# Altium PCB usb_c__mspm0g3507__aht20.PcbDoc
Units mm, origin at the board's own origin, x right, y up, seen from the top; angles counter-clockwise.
Board outline 68 x 40 mm, 2 copper layers (Top, Bottom), stack 0 mm thick; 38 components, 33 nets, 190 pads, 51 vias.
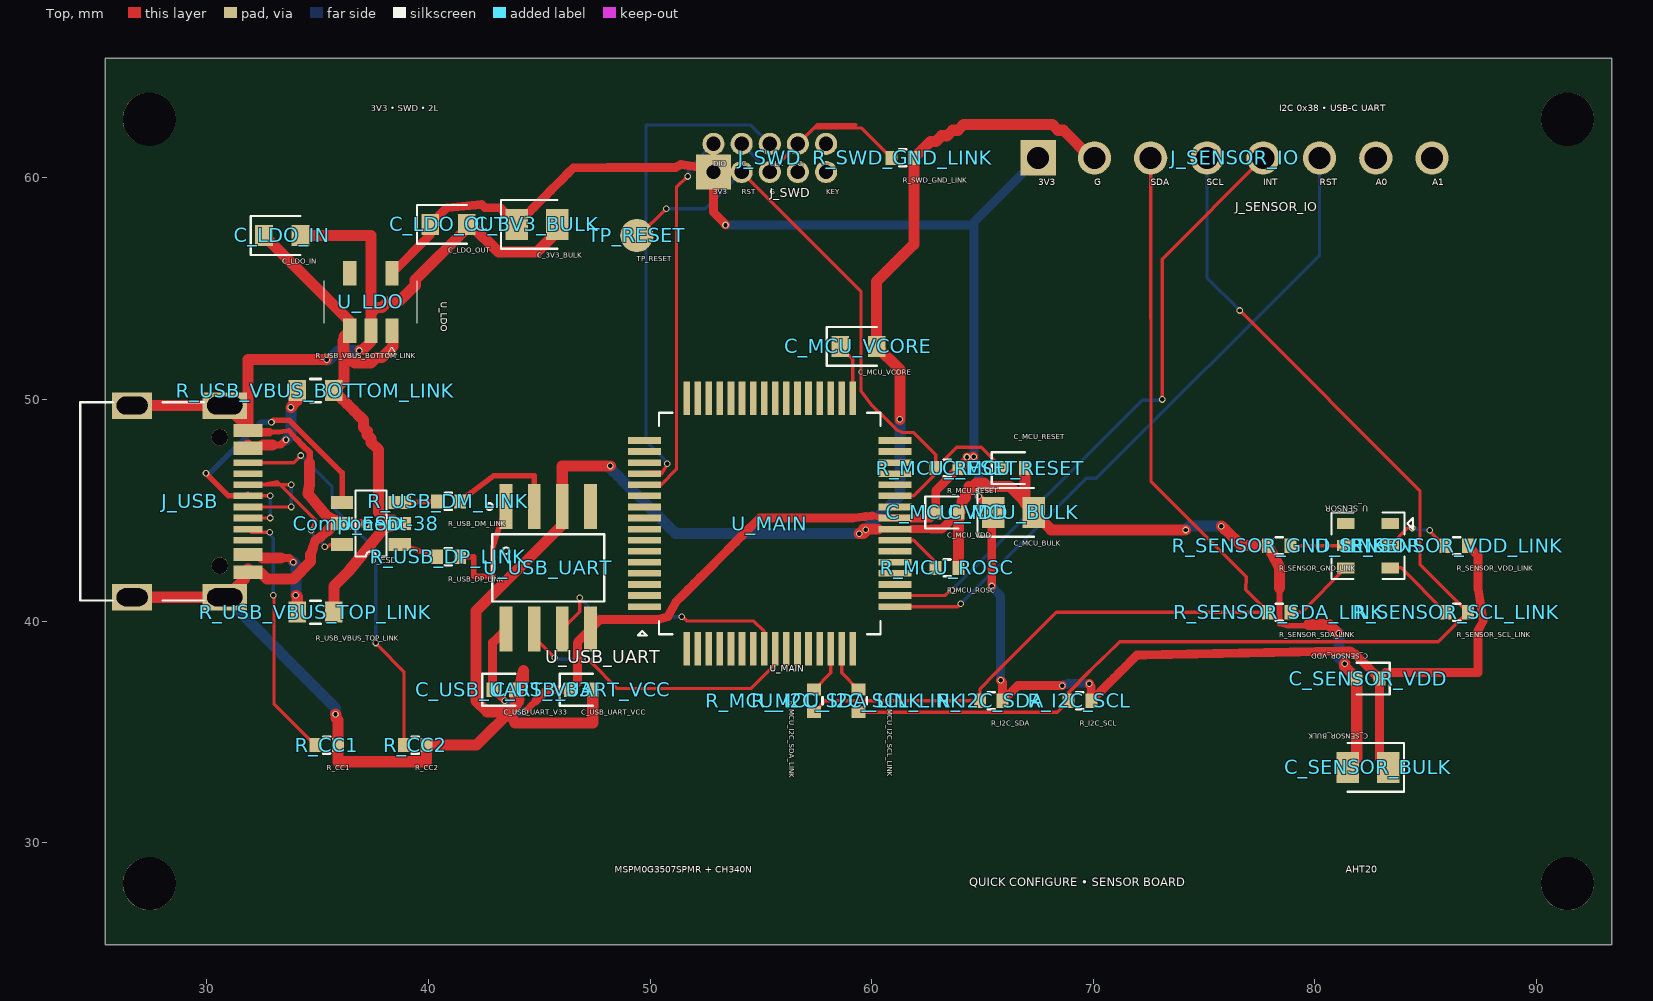
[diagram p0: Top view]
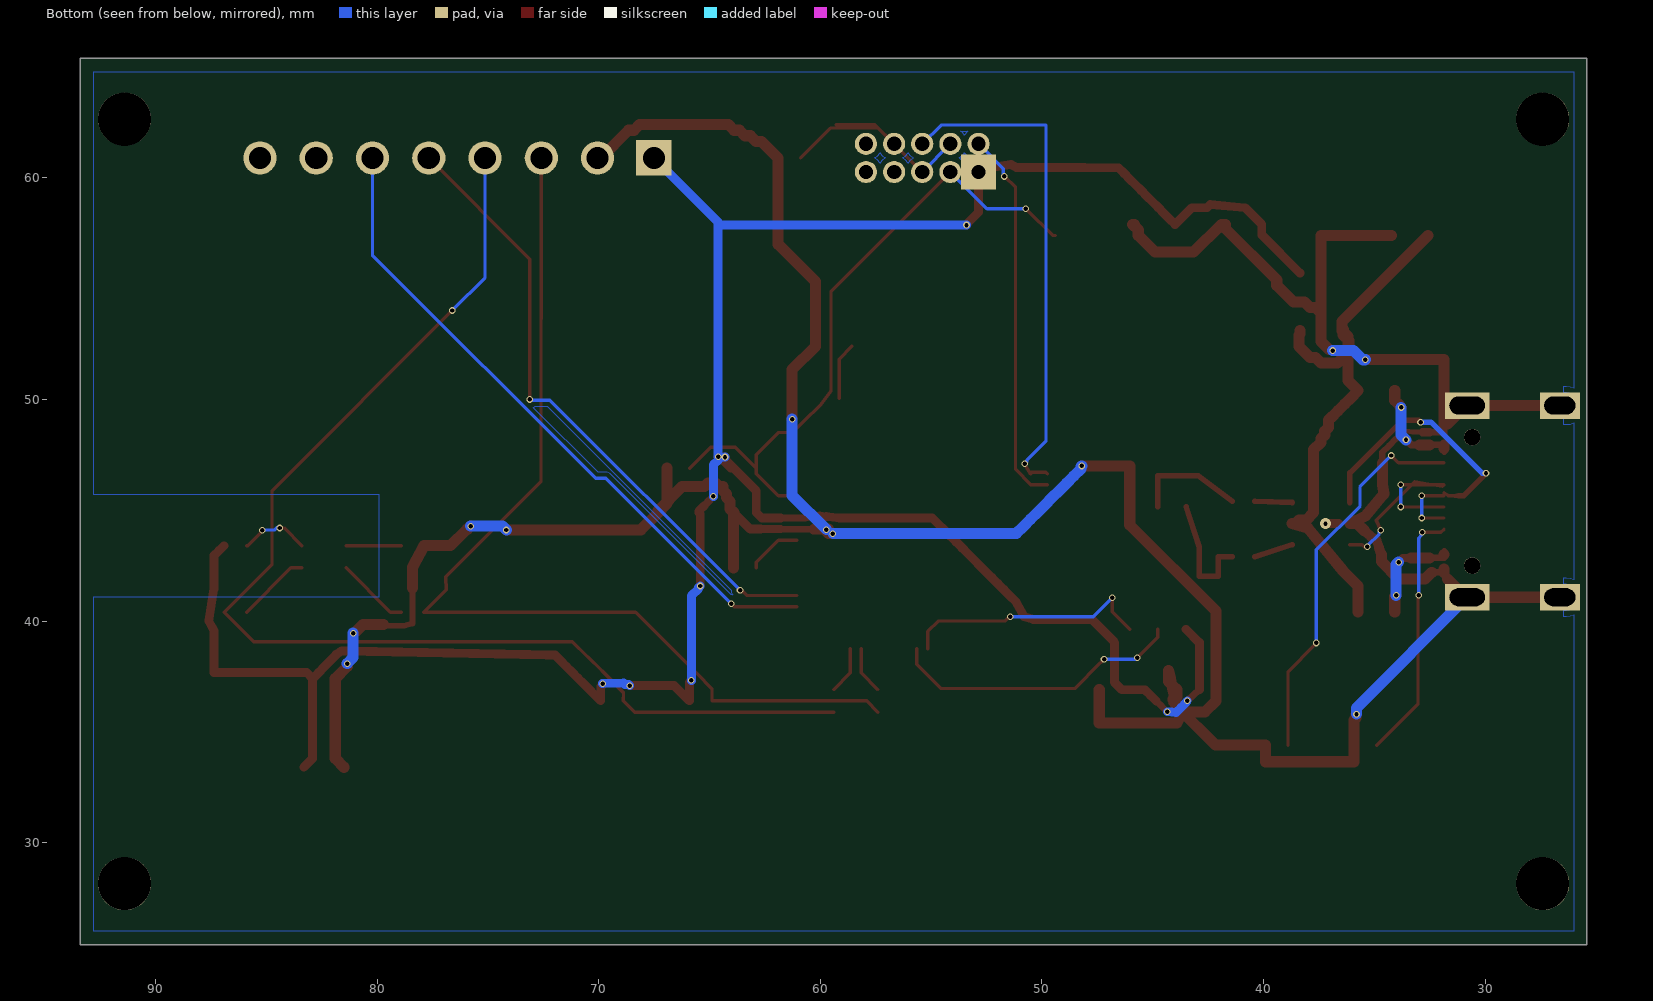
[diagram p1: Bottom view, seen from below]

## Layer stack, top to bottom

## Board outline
25.4,65.4 93.4,65.4 93.4,25.4 25.4,25.4

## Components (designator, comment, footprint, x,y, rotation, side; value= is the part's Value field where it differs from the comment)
C_3V3_BULK "" TSCIRCUIT-2.8500x1.4000mm 44.9,57.9 r0 top
C_LDO_IN "" TSCIRCUIT-2.4500x0.9500mm 33.4,57.4 r0 top
C_LDO_OUT "" TSCIRCUIT-2.4500x0.9500mm 40.9,57.9 r0 top
C_MCU_BULK "" TSCIRCUIT-2.8500x1.4000mm 66.4,44.9 r0 top
C_MCU_RESET "" TSCIRCUIT-1.5600x0.6400mm 66.4,46.9 r0 top
C_MCU_VCORE "" TSCIRCUIT-2.4500x0.9500mm 59.4,52.4 r0 top
C_MCU_VDD "" TSCIRCUIT-1.5600x0.6400mm 63.4,44.9 r0 top
C_SENSOR_BULK "" TSCIRCUIT-2.8500x1.4000mm 82.4,33.4 r180 top
C_SENSOR_VDD "" TSCIRCUIT-1.5600x0.6400mm 82.4,37.4 r180 top
C_USB_UART_V33 "" TSCIRCUIT-1.5600x0.6400mm 43.4,36.9 r0 top
C_USB_UART_VCC "" TSCIRCUIT-1.5600x0.6400mm 46.9,36.9 r0 top
Component-38 "" TSCIRCUIT-0.5000x0.5000mm 37.2,44.4 r0 top
J_SENSOR_IO "" TSCIRCUIT-19.2800x1.5000mm 76.4,60.9 r0 top
J_SWD "" TSCIRCUIT-6.0800x2.2700mm 55.4,60.9 r0 top
J_USB "" TSCIRCUIT-6.7732x9.8502mm 29.112,45.4 r90 top
R_CC1 "" TSCIRCUIT-1.5600x0.6400mm 35.4,34.4 r0 top
R_CC2 "" TSCIRCUIT-1.5600x0.6400mm 39.4,34.4 r0 top
R_I2C_SCL "" TSCIRCUIT-1.5600x0.6400mm 69.4,36.4 r0 top
R_I2C_SDA "" TSCIRCUIT-1.5600x0.6400mm 65.4,36.4 r0 top
R_MCU_I2C_SCL_LINK "" TSCIRCUIT-0.6400x1.5600mm 59.4,36.4 r270 top
R_MCU_I2C_SDA_LINK "" TSCIRCUIT-0.6400x1.5600mm 57.4,36.4 r270 top
R_MCU_RESET "" TSCIRCUIT-1.5600x0.6400mm 63.4,46.9 r0 top
R_MCU_ROSC "" TSCIRCUIT-1.5600x0.6400mm 63.4,42.4 r0 top
R_SENSOR_GND_LINK "" TSCIRCUIT-1.5600x0.6400mm 78.4,43.4 r0 top
R_SENSOR_SCL_LINK "" TSCIRCUIT-1.5600x0.6400mm 86.4,40.4 r0 top
R_SENSOR_SDA_LINK "" TSCIRCUIT-1.5600x0.6400mm 78.4,40.4 r0 top
R_SENSOR_VDD_LINK "" TSCIRCUIT-1.5600x0.6400mm 86.4,43.4 r0 top
R_SWD_GND_LINK "" TSCIRCUIT-1.5600x0.6400mm 61.4,60.9 r0 top
R_USB_DM_LINK "" TSCIRCUIT-1.5600x0.6400mm 40.9,45.4 r0 top
R_USB_DP_LINK "" TSCIRCUIT-1.5600x0.6400mm 40.9,42.9 r0 top
R_USB_VBUS_BOTTOM_LINK "" TSCIRCUIT-2.4500x0.9500mm 34.9,50.4 r0 top
R_USB_VBUS_TOP_LINK "" TSCIRCUIT-2.4500x0.9500mm 34.9,40.4 r0 top
TP_RESET "" TSCIRCUIT-1.5000x1.5000mm 49.4,57.4 r0 top
U_ESD "" TSCIRCUIT-3.6000x2.5000mm 37.4,44.4 r0 top
U_LDO "" TSCIRCUIT-2.5000x3.7000mm 37.4,54.4 r270 top
U_MAIN "" TSCIRCUIT-12.8000x12.8000mm 55.4,44.4 r0 top
U_SENSOR "" TSCIRCUIT-2.8000x2.5000mm 82.4,43.4 r0 top
U_USB_UART "" TSCIRCUIT-4.3840x7.5712mm 45.4,42.4 r0 top

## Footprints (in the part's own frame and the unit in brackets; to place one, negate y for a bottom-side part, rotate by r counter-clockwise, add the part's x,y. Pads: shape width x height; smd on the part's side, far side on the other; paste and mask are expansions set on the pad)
TSCIRCUIT-0.5000x0.5000mm [mm]
TSCIRCUIT-0.6400x1.5600mm [mm]
  rect 0.54x0.64 smd: 1(-0.51,0) 2(0.51,0)
  silkscreen extent -0.15,-0.38 0.15,0.38
TSCIRCUIT-1.5000x1.5000mm [mm]
  round 1.5 smd: 1(0,0)
TSCIRCUIT-1.5600x0.6400mm [mm]
  rect 0.54x0.64 smd: 1(-0.51,0) 2(0.51,0)
  silkscreen extent -0.98,-0.72 0.51,0.72
TSCIRCUIT-2.4500x0.9500mm [mm]
  rect 0.8x0.95 smd: 1(-0.825,0) 2(0.825,0)
  silkscreen extent -1.42,-0.87 0.82,0.87
TSCIRCUIT-2.5000x3.7000mm [mm]
  rect 1.1x0.6 smd: 1(1.3,0.95) 2(1.3,0) 3(1.3,-0.95) 4(-1.3,-0.95) 5(-1.3,0.95)
  silkscreen extent -0.95,-2.1 2.35,2.1
TSCIRCUIT-2.8000x2.5000mm [mm]
  rect 0.8x0.5 smd: 1(1,1) 2(1,0) 3(1,-1) 4(-1,-1) 5(-1,0) 6(-1,1)
  silkscreen extent -1.65,-1.5 2.02,1.5
TSCIRCUIT-2.8500x1.4000mm [mm]
  rect 1.025x1.4 smd: 1(-0.913,0) 2(0.913,0)
  silkscreen extent -1.62,-1.1 0.91,1.1
TSCIRCUIT-3.6000x2.5000mm [mm]
  rect 1x0.6 smd: 1(-1.3,-0.95) 2(-1.3,0) 3(-1.3,0.95) 4(1.3,0.95) 5(1.3,0) 6(1.3,-0.95)
  silkscreen extent -0.7,-1.49 0.7,1.49
TSCIRCUIT-4.3840x7.5712mm [mm]
  rect 0.574x2.036 smd: 1(-1.905,2.768) 2(-0.635,2.768) 3(0.635,2.768) 4(1.905,2.768) 5(1.905,-2.768) 6(0.635,-2.768) 7(-0.635,-2.768) 8(-1.905,-2.768)
  silkscreen extent -2.79,-1.52 2.53,2.92
TSCIRCUIT-6.0800x2.2700mm [mm]
  rect 1.6x1.6 hole 0.65: 1(-2.54,-0.635)
  round 1 hole 0.65: 2(-2.54,0.635) 3(-1.27,0.635) 4(0,0.635) 5(1.27,0.635) 6(2.54,0.635) 7(2.54,-0.635) 8(1.27,-0.635) 9(0,-0.635) 10(-1.27,-0.635)
TSCIRCUIT-6.7732x9.8502mm [mm]
  rect 0.3x1.3 smd: 1(-3.35,-2.737) 2(-3.05,-2.737) 3(-2.55,-2.737) 4(-2.25,-2.737) 5(-1.75,-2.737) 6(-1.25,-2.737) 7(-0.75,-2.737) 8(-0.25,-2.737) 9(0.25,-2.737) 10(0.75,-2.737) 11(1.25,-2.737) 12(1.75,-2.737) 13(2.55,-2.737) 14(2.25,-2.737) 15(3.35,-2.737) 16(3.05,-2.737)
  rect 1.2x2 hole 0.8 slot 1.6 at 90 deg: 17(-4.325,-1.693) 18(4.325,-1.693)
  rect 1.2x1.8 hole 0.8 slot 1.4 at 90 deg: 19(4.325,2.487) 20(-4.325,2.487)
  round 0.75 hole 0.75 unplated: NPTH-1(-2.9,-1.468) NPTH-2(2.9,-1.468)
  silkscreen extent -4.47,-0.75 4.47,4.83
TSCIRCUIT-12.8000x12.8000mm [mm]
  rect 1.5x0.3 smd: 1(-5.65,-3.75) 2(-5.65,-3.25) 3(-5.65,-2.75) 4(-5.65,-2.25) 5(-5.65,-1.75) 6(-5.65,-1.25) 7(-5.65,-0.75) 8(-5.65,-0.25) 9(-5.65,0.25) 10(-5.65,0.75) 11(-5.65,1.25) 12(-5.65,1.75) 13(-5.65,2.25) 14(-5.65,2.75) 15(-5.65,3.25) 16(-5.65,3.75) 33(5.65,3.75) 34(5.65,3.25) 35(5.65,2.75) 36(5.65,2.25) 37(5.65,1.75) 38(5.65,1.25) 39(5.65,0.75) 40(5.65,0.25) 41(5.65,-0.25) 42(5.65,-0.75) 43(5.65,-1.25) 44(5.65,-1.75) 45(5.65,-2.25) 46(5.65,-2.75) 47(5.65,-3.25) 48(5.65,-3.75)
  rect 0.3x1.5 smd: 17(-3.75,5.65) 18(-3.25,5.65) 19(-2.75,5.65) 20(-2.25,5.65) 21(-1.75,5.65) 22(-1.25,5.65) 23(-0.75,5.65) 24(-0.25,5.65) 25(0.25,5.65) 26(0.75,5.65) 27(1.25,5.65) 28(1.75,5.65) 29(2.25,5.65) 30(2.75,5.65) 31(3.25,5.65) 32(3.75,5.65) 49(3.75,-5.65) 50(3.25,-5.65) 51(2.75,-5.65) 52(2.25,-5.65) 53(1.75,-5.65) 54(1.25,-5.65) 55(0.75,-5.65) 56(0.25,-5.65) 57(-0.25,-5.65) 58(-0.75,-5.65) 59(-1.25,-5.65) 60(-1.75,-5.65) 61(-2.25,-5.65) 62(-2.75,-5.65) 63(-3.25,-5.65) 64(-3.75,-5.65)
  silkscreen extent -5.95,-5.05 5,5
TSCIRCUIT-19.2800x1.5000mm [mm]
  rect 1.6x1.6 hole 1: 1(-8.89,0)
  round 1.5 hole 1: 2(-6.35,0) 3(-3.81,0) 4(-1.27,0) 5(1.27,0) 6(3.81,0) 7(6.35,0) 8(8.89,0)

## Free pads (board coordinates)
  round 2.4 hole 2.4 unplated: NPTH-3(27.4,28.15) NPTH-4(91.4,28.15) NPTH-5(27.4,62.65) NPTH-6(91.4,62.65)

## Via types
v1: diameter 0.3, hole 0.2, Top to Bottom, 50 vias
v2: diameter 0.5, hole 0.2, Top to Bottom, 1 vias

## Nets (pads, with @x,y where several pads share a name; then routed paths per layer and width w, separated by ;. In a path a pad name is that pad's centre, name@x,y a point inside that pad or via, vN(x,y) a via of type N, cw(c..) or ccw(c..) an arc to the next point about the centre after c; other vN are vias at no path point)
".J_SWD > .pin2 to .U_MAIN > .pin12": J_SWD.2 U_MAIN.12 | length 17.1
  Top w0.15: U_MAIN.12 50.496,46.15 51.188,46.842 51.188,59.575 v1(51.697,60.066)
  Bottom w0.15: v1(51.697,60.066) 51.741,60.128 51.741,60.248 51.741,60.416 J_SWD.2
".J_SWD > .pin4 to .U_MAIN > .pin13": J_SWD.4 U_MAIN.13 | length 23
  Top w0.15: U_MAIN.13 49.817,46.717 50.519,46.717 50.509,46.646 50.708,46.977 v1(50.775,47.104)
  Bottom w0.15: v1(50.775,47.104) 50.687,47.192 50.687,47.246 49.816,48.117 49.816,62.384 54.551,62.384 J_SWD.4
".U_MAIN > .pin42 to .R_MCU_ROSC > .pin1": R_MCU_ROSC.1 U_MAIN.42 | length 2.5
  Top w0.15: U_MAIN.42 61.889,43.65 62.89,42.649 R_MCU_ROSC.1
AHT_GND_LOCAL: R_SENSOR_GND_LINK.2 U_SENSOR.5 | length 2.5
  Top w0.15: R_SENSOR_GND_LINK.2 U_SENSOR.5
AHT_SCL_LOCAL: R_SENSOR_SCL_LINK.1 U_SENSOR.3 | length 3.3
  Top w0.15: U_SENSOR.3 83.89,42.4 R_SENSOR_SCL_LINK.1
AHT_SDA_LOCAL: R_SENSOR_SDA_LINK.2 U_SENSOR.4 | length 3.3
  Top w0.15: R_SENSOR_SDA_LINK.2 79.4,40.4 U_SENSOR.4
AHT_VDD_LOCAL: R_SENSOR_VDD_LINK.1 U_SENSOR.2 | length 3.2
  Top w0.15: U_SENSOR.2 84.2,44.2 v1(84.4,44.2) ; v1(85.189,44.105) 85.193,44.101 85.193,44.051 85.844,43.4 R_SENSOR_VDD_LINK.1
  Bottom w0.15: v1(84.4,44.2) 84.443,44.243 84.498,44.243 84.635,44.105 v1(85.189,44.105)
GND: C_3V3_BULK.2 C_LDO_IN.2 C_LDO_OUT.2 C_MCU_BULK.2 C_MCU_RESET.2 C_MCU_VCORE.2 C_MCU_VDD.2 C_SENSOR_BULK.2 C_SENSOR_VDD.2 C_USB_UART_V33.2 C_USB_UART_VCC.2 J_SENSOR_IO.2 J_USB.1 J_USB.2 J_USB.15 J_USB.16 J_USB.17 J_USB.18 J_USB.19 J_USB.20 R_CC1.2 R_CC2.2 R_MCU_ROSC.2 R_SENSOR_GND_LINK.1 R_SWD_GND_LINK.2 U_ESD.2 U_LDO.2 U_MAIN.41 U_USB_UART.3 | length 181.6
  Top w0.225: 32.823,48.524 33.276,48.526 33.7,48.6 33.865,48.412 34.03,48.224
  Top w0.25: 78.4,39.9 78.765,39.792 79.658,39.792
  Top w0.275: J_USB.16 J_USB.16@31.918,48.52 ; 34.03,48.224 34.331,47.92 34.632,47.616 ; 78.4,39.9 78.4,40.237 78.4,40.575 78.4,41.038 78.4,41.501 ; 79.658,39.792 79.712,39.846
  Top w0.3: J_USB.1@31.699,41.9 J_USB.1 J_USB.1@31.849,42.2 ; J_USB.15@31.699,48.9 J_USB.15 ; J_USB.16@31.849,48.6 J_USB.15 ; J_USB.15@31.849,48.9 J_USB.15 ; J_USB.2@31.995,42.204 32.001,42.198 J_USB.1@32.406,42.198 ; 34.632,47.133 34.632,47.616 ; 60.238,44.15 60.644,44.15 U_MAIN.41 ; U_MAIN.41@60.3,44.15 60.58,44.15 U_MAIN.41 ; 61.8,44.15 61.706,44.15 61.613,44.15 61.519,44.15 61.425,44.15 61.331,44.15 61.238,44.15 61.144,44.15 U_MAIN.41
  Top w0.306: J_USB.16@31.918,48.52 32.371,48.522 J_USB.16@32.499,48.522
  Top w0.325: J_USB.2 J_USB.2@31.995,42.204 ; J_USB.16 J_USB.16@31.849,48.6
  Top w0.375: 32.499,48.522 32.823,48.524 ; 61.8,44.15 62.253,44.15 62.707,44.15
  Top w0.4: 36.6,44.4 37.2,44.4 ; v1(36.878,52.207) v1@36.879,52.252 ; 62.707,44.15 63.16,44.15 63.41,44.4 63.66,44.65 C_MCU_VDD.2
  Top w0.425: v1@36.879,52.252 37.034,52.252 ; 80.949,39.534 80.999,39.534 v1(81.082,39.451)
  Top w0.437: 34.791,43.322 34.9,43.65 35.138,43.799
  Top w0.45: 34.681,42.994 34.791,43.322 ; 35.138,43.799 35.439,44.073
  Top w0.475: v1@59.831,44.15 60.238,44.15 ; 60.109,44.15 60.3,44.15
  Top w0.5: J_USB.20 J_USB.17 ; J_USB.19 J_USB.18 ; J_USB.17 30.874,41.075 31.474,41.675 31.699,41.9 ; J_USB.18 30.874,49.725 31.474,49.125 31.699,48.9 ; J_USB.1@31.849,42.2 J_USB.2 ; 31.849,48.9 31.849,51.8 v1(35.4,51.8) ; J_USB.1@32.406,42.198 32.703,41.9 33.9,41.9 34.681,42.681 34.681,42.994 ; C_LDO_IN.2 37.4,57.4 U_LDO.2 ; 34.632,47.133 34.632,46.649 34.632,46.166 34.567,45.733 35.4,44.733 U_ESD.2 35.78,44.406 35.439,44.073 ; v1(35.8,35.8) 35.83,35.77 35.83,35.617 35.91,35.537 R_CC1.2 35.91,33.65 39.91,33.65 R_CC2.2 42.166,34.4 43.869,36.103 44.087,36.431 ; 37.034,52.252 37.217,52.435 37.4,52.618 U_LDO.2 ; C_3V3_BULK.2 45.9,57.9 45.65,57.65 45.65,57.4 44.9,56.65 43.15,56.65 41.9,57.9 C_LDO_OUT.2 41.725,57.725 39.4,55.4 39.4,55.15 38.65,54.4 38.15,54.4 37.9,54.15 37.65,54.15 37.4,53.9 U_LDO.2 ; C_USB_UART_VCC.2 47.41,35.4 43.9,35.4 43.65,35.9 ; v1(48.2,47) 46.035,47 U_USB_UART.3 46.035,44.749 46.035,44.33 42.15,40.445 42.15,36.4 42.65,35.9 43.65,35.9 ; v1(59.434,43.945) 59.44,43.951 59.633,43.951 v1@59.831,44.15 ; v1(59.725,44.125) 59.664,44.125 59.639,44.15 60.109,44.15 ; v1(61.271,49.107) 61.271,51.354 C_MCU_VCORE.2 60.225,52.887 60.225,53.374 60.225,53.86 60.225,54.347 60.225,54.834 60.225,55.321 61.91,57.006 R_SWD_GND_LINK.2 62.247,61.237 62.584,61.574 62.65,61.64 62.65,61.65 62.9,61.65 63.15,61.9 63.4,61.9 63.65,62.15 63.9,62.15 64.15,62.4 68.15,62.4 68.4,62.15 68.65,62.15 69.9,60.9 J_SENSOR_IO.2 ; R_MCU_ROSC.2 C_MCU_VDD.2 63.9,44.9 64.067,45.067 64.067,45.4 64.233,45.567 64.233,45.733 64.4,45.9 64.4,46.067 64.567,46.067 64.733,46.233 65.067,46.233 65.233,46.067 66.233,46.067 67.312,44.988 C_MCU_BULK.2 ; C_MCU_RESET.2 66.91,45.303 C_MCU_BULK.2 ; v1(74.169,44.108) 68.104,44.108 C_MCU_BULK.2 ; v1(75.778,44.285) 75.92,44.143 75.948,44.143 76.691,43.4 R_SENSOR_GND_LINK.1 78.4,42.427 78.4,41.964 78.4,41.501 ; 79.712,39.846 80.175,39.846 80.637,39.846 80.949,39.534 ; v1(81.349,38.079) 81.349,37.941 C_SENSOR_VDD.2 81.89,33.803 C_SENSOR_BULK.2 ; 43.65,35.9 43.9,36.15 44.087,36.431 ; 43.65,35.9 43.817,36.067 43.942,36.213 44.028,36.603 44.114,36.993 44.201,37.383 44.287,37.773 44.287,37.277 44.098,37.088 C_USB_UART_V33.2 ; C_USB_UART_V33.2 43.999,36.666 44.087,36.431 ; C_USB_UART_V33.2 43.912,36.582 44.087,36.431
  Bottom w0.5: J_USB.17 35.8,36.081 v1(35.8,35.8) ; v1(35.4,51.8) 35.423,51.777 35.505,51.777 35.72,51.992 35.935,52.207 36.406,52.207 v1(36.878,52.207) ; v1(48.2,47) 48.237,46.963 48.237,46.866 48.562,46.542 48.886,46.217 49.211,45.893 49.535,45.568 49.86,45.243 50.185,44.919 50.509,44.594 50.834,44.27 51.158,43.945 51.645,43.945 52.132,43.945 52.619,43.945 53.106,43.945 53.592,43.945 54.079,43.945 54.566,43.945 55.053,43.945 55.54,43.945 56.026,43.945 56.513,43.945 57,43.945 57.487,43.945 57.974,43.945 58.46,43.945 58.947,43.945 v1(59.434,43.945) ; v1(59.725,44.125) 61.271,45.671 v1(61.271,49.107) ; v1(74.169,44.108) 74.346,44.285 v1(75.778,44.285) ; v1(81.082,39.451) 81.082,38.346 v1(81.349,38.079)
MAIN_RESET: C_MCU_RESET.1 J_SWD.10 R_MCU_RESET.1 TP_RESET.1 U_MAIN.38 | length 29.5
  Top w0.15: TP_RESET.1 49.52,57.4 50.672,58.553 50.672,58.562 v1(50.724,58.614) ; J_SWD.10 59.516,54.879 59.516,50.496 59.516,50.383 59.987,49.756 60.763,48.993 61.134,48.622 61.388,48.512 61.876,48.512 62.89,47.498 R_MCU_RESET.1 63.828,47.838 64.952,47.838 C_MCU_RESET.1 ; U_MAIN.38 61.889,45.65 62.89,46.651 R_MCU_RESET.1@62.89,46.9
  Bottom w0.15: v1(50.724,58.614) 52.479,58.614 J_SWD.10
MCU_I2C_SCL_LOCAL: R_MCU_I2C_SCL_LINK.1 U_MAIN.50 | length 2.2
  Top w0.15: U_MAIN.50 58.65,37.66 R_MCU_I2C_SCL_LINK.1
MCU_I2C_SDA_LOCAL: R_MCU_I2C_SDA_LINK.1 U_MAIN.51 | length 2.2
  Top w0.15: R_MCU_I2C_SDA_LINK.1 58.15,37.66 U_MAIN.51
MSPM0_VCORE: C_MCU_VCORE.1 U_MAIN.32 | length 2.6
  Top w0.15: C_MCU_VCORE.1 59.15,51.825 U_MAIN.32
SENSOR_ADDR0: J_SENSOR_IO.7
SENSOR_ADDR1: J_SENSOR_IO.8
SENSOR_INT: J_SENSOR_IO.5 U_MAIN.47 | length 28.5
  Top w0.15: U_MAIN.47 63.299,41.15 63.476,41.328 63.566,41.328 v1(63.621,41.383) ; v1(73.106,50.001) 73.106,56.336 J_SENSOR_IO.5
  Bottom w0.15: v1(63.621,41.383) 72.2,49.962 73.066,49.962 v1(73.106,50.001)
SENSOR_RESET: J_SENSOR_IO.6 U_MAIN.48 | length 30.1
  Top w0.15: U_MAIN.48 63.879,40.65 64,40.771 64.005,40.771 v1(64.017,40.783)
  Bottom w0.15: v1(64.017,40.783) 69.68,46.446 70.143,46.446 80.21,56.512 J_SENSOR_IO.6
SENSOR_SCL: J_SENSOR_IO.4 R_I2C_SCL.1 R_MCU_I2C_SCL_LINK.2 R_SENSOR_SCL_LINK.2 | length 55
  Top w0.15: R_MCU_I2C_SCL_LINK.2 68.38,35.89 R_I2C_SCL.1 68.882,36.771 69.853,37.762 71.19,39.063 85.573,39.063 R_SENSOR_SCL_LINK.2 84.742,42.568 84.742,42.634 84.742,45.89 v1(76.616,54.016)
  Bottom w0.15: J_SENSOR_IO.4 75.13,55.502 v1(76.616,54.016)
SENSOR_SDA: J_SENSOR_IO.3 R_I2C_SDA.1 R_MCU_I2C_SDA_LINK.2 R_SENSOR_SDA_LINK.1 | length 45.4
  Top w0.15: R_MCU_I2C_SDA_LINK.2 57.91,36.4 R_I2C_SDA.1 64.89,36.953 65.559,37.622 68.337,40.4 R_SENSOR_SDA_LINK.1 76.888,41.402 76.9,41.996 72.605,46.298 J_SENSOR_IO.3
swd-ground-1-to-2: J_SWD.3 J_SWD.5 J_SWD.9 R_SWD_GND_LINK.1 | length 14.6
  Top w0.15: J_SWD.9 57.54,62.405 ; R_SWD_GND_LINK.1 59.543,62.247 59.375,62.247 57.382,62.247 J_SWD.5 57.54,62.405 ; 57.54,62.405 59.277,62.405 57.54,62.405
  Bottom w0.15: J_SWD.3 J_SWD.9
UART_MSP_RX: U_MAIN.57 U_USB_UART.6 | length 11.5
  Top w0.15: U_USB_UART.6 46.828,40.425 v1(46.828,41.05) ; v1(51.428,40.2) 51.458,40.17 51.5,40.17 51.67,40 54.679,40 55.15,39.529 U_MAIN.57
  Bottom w0.15: v1(46.828,41.05) 47.678,40.2 v1(51.428,40.2)
UART_MSP_TX: U_MAIN.56 U_USB_UART.7 | length 13.4
  Top w0.15: U_USB_UART.7 44.765,39.269 v1(45.694,38.34) ; v1(47.195,38.277) 47.352,38.11 47.361,38.11 48.516,36.955 54.553,36.955 55.65,38.052 U_MAIN.56
  Bottom w0.15: v1(45.694,38.34) 45.702,38.332 45.709,38.332 45.764,38.277 v1(47.195,38.277)
usb-dm-device: R_USB_DM_LINK.1 U_ESD.4 | length 1.7
  Top w0.25: U_ESD.4 R_USB_DM_LINK.1
usb-dm-port-tie: J_USB.7 J_USB.9 U_ESD.3 | length 15
  Top w0.15: J_USB.9@31.349,45.65 31.38,45.65 31.474,45.65 31.568,45.65 31.662,45.65 31.615,45.65 31.849,45.79 J_USB.9 v1(32.85,45.65) ; J_USB.7 v1(32.85,44.65)
  Top w0.175: J_USB.9@31.287,45.65 J_USB.9@31.349,45.65
  Top w0.212: 31.193,45.65 J_USB.9@31.287,45.65
  Top w0.25: v1(29.956,46.662) 30.968,45.65 31.099,45.65 31.193,45.65 ; v1(32.911,48.979) 32.975,49.043 32.982,49.043 32.996,49.057 33.725,49.057 36.1,46.683 U_ESD.3
  Bottom w0.15: v1(32.85,44.65) v1(32.85,45.65)
  Bottom w0.25: v1(29.956,46.662) 30.123,46.662 32.44,48.979 v1(32.911,48.979)
usb-dm-uart: R_USB_DM_LINK.2 U_USB_UART.2 | length 5.1
  Top w0.25: R_USB_DM_LINK.2 42.95,46.55 44.765,46.55 U_USB_UART.2
usb-dp-device: R_USB_DP_LINK.1 U_ESD.6 | length 1.8
  Top w0.25: U_ESD.6 R_USB_DP_LINK.1
usb-dp-port-tie: J_USB.8 J_USB.10 U_ESD.1 | length 11.1
  Top w0.15: J_USB.8 v1(33.8,45.15) ; v1(33.8,46.15) J_USB.10 31.923,46.076 33.182,46.28 34.909,44.545 v1(34.707,44.1) ; v1(35.309,43.35) 35.35,43.309 35.409,43.309 35.55,43.45 U_ESD.1
  Bottom w0.15: v1(33.8,45.15) v1(33.8,46.15) ; v1(34.707,44.1) 34.785,44.022 34.785,43.917 35.284,43.418 v1(35.309,43.35)
usb-dp-uart: R_USB_DP_LINK.2 U_USB_UART.1 | length 5.6
  Top w0.25: R_USB_DP_LINK.2 42.05,42.9 42.05,42.03 42.9,42.03 42.9,43.35 U_USB_UART.1
USB_CC1: J_USB.6 R_CC1.1 | length 11.5
  Top w0.15: J_USB.6 31.995,44.004 v1(32.827,44.004) ; v1(32.989,41.16) 33.023,41.126 33.023,36.267 R_CC1.1
  Bottom w0.15: v1(32.827,44.004) 32.873,43.958 32.873,43.861 32.989,43.745 v1(32.989,41.16)
USB_CC2: J_USB.12 R_CC2.1 | length 17.5
  Top w0.15: J_USB.12 33.907,47.15 v1(34.227,47.47) ; v1(37.621,39.012) 37.697,38.936 37.697,38.906 38.89,37.713 R_CC2.1
  Bottom w0.15: v1(34.227,47.47) 34.312,47.385 35.646,46.051 35.643,45.19 37.617,43.213 v1(37.621,39.012)
USB_VBUS_BOTTOM_LOCAL: J_USB.13 J_USB.14 R_USB_VBUS_BOTTOM_LINK.1 | length 4.5
  Top w0.3: J_USB.14 J_USB.14@31.849,47.8 ; J_USB.13 31.943,47.95 32.036,47.95 32.13,47.95 32.224,47.95 32.318,47.95 32.411,47.95 J_USB.13@32.499,47.95
  Top w0.325: 32.966,47.95 33.333,47.95 v1(33.568,48.175)
  Top w0.475: J_USB.13@31.849,47.8 J_USB.13
  Top w0.5: 32.499,47.95 32.505,47.95 32.599,47.95 32.966,47.95 ; v1(33.787,49.64) 33.855,49.708 33.855,49.741 34.075,49.962 R_USB_VBUS_BOTTOM_LINK.1
  Bottom w0.5: v1(33.568,48.175) 33.787,48.394 v1(33.787,49.64)
USB_VBUS_TOP_LOCAL: J_USB.3 J_USB.4 R_USB_VBUS_TOP_LINK.1 | length 4.8
  Top w0.3: J_USB.4 31.849,43 J_USB.3 J_USB.3@31.946,42.868 ; J_USB.3@32.037,42.85 32.13,42.85 32.224,42.85 32.318,42.85 32.411,42.85 J_USB.3@32.499,42.85
  Top w0.301: J_USB.3@31.946,42.868 J_USB.3@32.037,42.85
  Top w0.35: 33.342,42.85 33.713,42.85 v1(33.902,42.66)
  Top w0.5: 32.499,42.85 32.505,42.85 32.599,42.85 32.97,42.85 33.342,42.85 ; v1(34.013,41.16) 34.075,41.098 R_USB_VBUS_TOP_LINK.1
  Bottom w0.5: v1(33.902,42.66) 34.013,42.549 v1(34.013,41.16)
VBUS5: C_LDO_IN.1 R_USB_VBUS_BOTTOM_LINK.2 R_USB_VBUS_TOP_LINK.2 U_ESD.5 U_LDO.1 U_LDO.3 | length 26.6
  Top w0.5: C_LDO_IN.1 36.45,53.525 U_LDO.3 ; R_USB_VBUS_TOP_LINK.2 35.725,40.793 35.725,41.185 35.725,41.578 36.069,41.922 36.413,42.266 38,44.2 U_ESD.5 38.567,44.4 38.4,44.567 38.067,44.567 37.733,44.9 37.733,47.733 37.4,48.067 37.4,48.233 37.233,48.4 37.233,48.567 37.067,48.733 37.067,49.067 36.9,49.233 36.9,49.225 36.938,49.187 36.634,49.491 36.331,49.794 36.028,50.097 R_USB_VBUS_BOTTOM_LINK.2 36.19,50.865 36.19,50.883 36.19,52.84 U_LDO.3 ; U_LDO.1 38.35,52.95 38.4,52.9 38.4,52.4 37.9,51.9 37.65,51.9 37.4,51.65 36.65,51.65 36.15,52.15 36.15,52.65 36.4,52.9 36.4,53.15 U_LDO.3
VCC_3V3: C_3V3_BULK.1 C_LDO_OUT.1 C_MCU_BULK.1 C_MCU_VDD.1 C_SENSOR_BULK.1 C_SENSOR_VDD.1 C_USB_UART_V33.1 C_USB_UART_VCC.1 J_SENSOR_IO.1 J_SWD.1 R_I2C_SCL.2 R_I2C_SDA.2 R_MCU_RESET.2 R_SENSOR_VDD_LINK.2 U_LDO.5 U_MAIN.40 U_USB_UART.5 U_USB_UART.8 | length 128.8
  Top w0.3: C_USB_UART_V33.1 43.163,36.651 v1(43.437,36.403) ; v1(44.34,35.905) 44.585,36.139 44.841,36.393 ; U_MAIN.40@60.346,44.7 60.669,44.65 U_MAIN.40 61.15,44.65 61.25,44.65 61.35,44.65 61.45,44.65 61.55,44.65 61.65,44.65 61.75,44.65 61.8,44.65 ; v1(64.825,45.628) 64.847,45.606 v1@64.847,45.597
  Top w0.312: 60.023,44.75 U_MAIN.40@60.346,44.7
  Top w0.337: v1@64.847,45.597 C_MCU_BULK.1@65.061,45.384
  Top w0.363: C_MCU_BULK.1@65.061,45.384 C_MCU_BULK.1@65.274,45.17
  Top w0.375: 59.73,44.717 60.023,44.75
  Top w0.4: U_LDO.5 40.075,57.425 C_LDO_OUT.1 40.327,58.152 40.578,58.403 40.83,58.655 42.4,58.8 42.546,58.655 42.89,58.655 43.233,58.655 43.484,58.403 43.736,58.152 C_3V3_BULK.1 44.243,58.156 44.499,58.412 44.754,58.667 45.01,58.923 45.265,59.179 45.521,59.435 45.776,59.69 46.032,59.946 46.287,60.202 46.543,60.458 46.926,60.458 47.309,60.459 47.692,60.46 48.075,60.461 48.458,60.462 48.841,60.462 49.224,60.463 49.606,60.464 49.989,60.465 50.372,60.465 50.755,60.466 51.138,60.467 51.4,60.6 52.287,60.469 52.67,60.47 J_SWD.1 52.86,58.449 53.344,57.965 53.344,57.931 v1(53.403,57.872) ; C_USB_UART_V33.1 42.89,39.027 U_USB_UART.8 ; 44.841,36.393 45.097,36.646 45.353,36.9 45.698,36.9 46.044,36.9 C_USB_UART_VCC.1 46.731,37.245 46.729,39.007 46.735,39.062 U_USB_UART.5 47.525,39.853 47.746,40.073 48.121,40.073 48.496,40.073 48.871,40.073 49.246,40.073 49.622,40.073 49.997,40.073 50.372,40.073 50.8,40.2 51.18,40.881 51.449,41.15 51.718,41.419 51.987,41.688 52.256,41.958 52.526,42.227 52.795,42.496 53.064,42.765 53.333,43.035 53.603,43.304 53.872,43.573 54.141,43.842 54.41,44.112 54.68,44.381 54.949,44.65 55.33,44.65 55.712,44.65 56.093,44.65 56.474,44.65 56.855,44.65 57.237,44.65 57.618,44.65 57.999,44.65 58.381,44.65 58.762,44.65 59.143,44.65 59.437,44.683 59.73,44.717 ; 61.8,44.65 61.85,44.65 62.64,44.65 C_MCU_VDD.1 62.89,45.88 R_MCU_RESET.2 ; v1(64.3,47.4) 64.427,47.417 64.168,47.158 R_MCU_RESET.2 ; v1(64.613,47.417) 64.58,47.448 64.031,46.9 R_MCU_RESET.2 ; C_MCU_BULK.1@65.274,45.17 65.487,44.957 C_MCU_BULK.1 65.42,44.832 v1(65.42,41.581) ; v1(65.819,37.324) 65.91,37.233 65.91,37.15 R_I2C_SDA.2 66.596,37.086 v1(68.601,37.086) ; v1(69.824,37.176) 69.836,37.164 69.834,37.119 69.91,37.043 R_I2C_SCL.2 70.168,36.658 70.425,36.915 70.683,37.173 70.94,37.431 71.198,37.689 71.455,37.946 71.713,38.204 71.97,38.462 72.356,38.469 72.741,38.477 73.126,38.484 73.511,38.492 73.896,38.499 74.282,38.507 74.667,38.514 75.052,38.522 75.437,38.529 75.822,38.537 76.207,38.545 76.593,38.552 76.978,38.56 77.363,38.567 77.748,38.575 78.133,38.582 78.519,38.59 78.904,38.597 79.289,38.605 79.674,38.612 80.059,38.62 80.444,38.627 80.83,38.635 81.215,38.642 81.6,38.65 81.85,38.483 82.115,38.212 82.38,37.941 82.645,37.671 C_SENSOR_VDD.1 ; C_SENSOR_BULK.1 82.91,33.803 C_SENSOR_VDD.1 ; R_SENSOR_VDD_LINK.2 87.14,43.178 87.37,42.955 87.37,42.578 87.37,42.201 87.37,41.825 87.37,41.448 87.6,40 87.37,39.564 87.37,39.187 87.37,38.81 87.37,38.433 87.37,38.057 87.37,37.68 86.99,37.68 86.61,37.68 86.23,37.68 85.85,37.68 85.47,37.68 85.09,37.68 84.71,37.68 84.33,37.68 83.95,37.68 83.57,37.68 83.19,37.68 C_SENSOR_VDD.1
  Bottom w0.4: v1(43.437,36.403) 43.498,36.316 43.5,36.316 43.72,36.096 43.94,35.876 44.14,35.89 v1(44.34,35.905) ; v1(53.403,57.872) 64.482,57.872 J_SENSOR_IO.1 64.613,58.003 v1(64.613,47.417) ; v1(64.3,47.4) 64.59,47.394 64.59,47.281 64.824,47.047 64.824,46.692 64.825,46.337 64.825,45.982 v1(64.825,45.628) ; v1(65.42,41.581) 65.491,41.51 65.491,41.462 65.819,41.135 v1(65.819,37.324) ; v1(68.601,37.086) 68.653,37.138 68.827,37.138 68.889,37.2 v1(69.824,37.176)
pads on no net: J_SWD.6 J_SWD.7 J_SWD.8 J_USB.5 J_USB.11 J_USB.NPTH-1 J_USB.NPTH-2 U_LDO.4 U_MAIN.1 U_MAIN.2 U_MAIN.3 U_MAIN.4 U_MAIN.5 U_MAIN.6 U_MAIN.7 U_MAIN.8 U_MAIN.9 U_MAIN.10 U_MAIN.11 U_MAIN.14 U_MAIN.15 U_MAIN.16 U_MAIN.17 U_MAIN.18 U_MAIN.19 U_MAIN.20 U_MAIN.21 U_MAIN.22 U_MAIN.23 U_MAIN.24 U_MAIN.25 U_MAIN.26 U_MAIN.27 U_MAIN.28 U_MAIN.29 U_MAIN.30 U_MAIN.31 U_MAIN.33 U_MAIN.34 U_MAIN.35 U_MAIN.36 U_MAIN.37 U_MAIN.39 U_MAIN.43 U_MAIN.44 U_MAIN.45 U_MAIN.46 U_MAIN.49 U_MAIN.52 U_MAIN.53 U_MAIN.54 U_MAIN.55 U_MAIN.58 U_MAIN.59 U_MAIN.60 U_MAIN.61 U_MAIN.62 U_MAIN.63 U_MAIN.64 U_SENSOR.1 U_SENSOR.6 U_USB_UART.4
copper on no net:
  other v2: 37.2,44.4

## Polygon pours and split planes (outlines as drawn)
GND on Bottom (solid): 92.8,64.8 26,64.8 26,50.51 26.001,50.51 26.16,50.559 26.326,50.575 26.476,50.575 26.476,50.325 26.326,50.325 26.209,50.314 26.096,50.279 26,50.228 26,49.222 26.096,49.171 26.209,49.137 26.326,49.125 26.476,49.125 26.476,48.875 26.326,48.875 26.16,48.891 26.001,48.94 26,48.94 26,41.86 26.001,41.86 26.16,41.909 26.326,41.925 26.476,41.925 26.476,41.675 26.326,41.675 26.209,41.663 26.096,41.629 26,41.578 26,40.572 26.096,40.521 26.209,40.486 26.326,40.475 26.476,40.475 26.476,40.225 26.326,40.225 26.16,40.241 26.001,40.29 26,40.29 26,26 92.8,26 92.8,41.1 80.2,41.1 79.9,41.1 79.9,41.4 79.9,45.1 79.9,45.7 80.5,45.7 92.8,45.7
GND on Bottom (solid): 53.653,62.109 53.337,62.109 53.39,62.065 53.484,61.952 53.495,61.93 53.506,61.952 53.6,62.065
GND on Bottom (solid): 53.495,61.14 53.484,61.118 53.399,61.015 53.591,61.015 53.506,61.118
GND on Bottom (solid): 53.61,60.996 53.61,60.804 53.713,60.889 53.735,60.9 53.713,60.911
GND on Bottom (solid): 57.305,61.14 57.294,61.118 57.2,61.005 57.087,60.911 57.065,60.9 57.087,60.889 57.2,60.795 57.294,60.682 57.305,60.66 57.316,60.682 57.41,60.795 57.523,60.889 57.545,60.9 57.523,60.911 57.41,61.005 57.316,61.118
GND on Bottom (solid): 56.035,61.14 56.024,61.118 55.93,61.005 55.817,60.911 55.795,60.9 55.817,60.889 55.93,60.795 56.024,60.682 56.035,60.66 56.046,60.682 56.14,60.795 56.253,60.889 56.275,60.9 56.253,60.911 56.14,61.005 56.046,61.118
GND on Bottom (solid): 72.861,49.687 72.314,49.687 64.02,41.393 64.021,41.383 64.013,41.305 63.991,41.23 63.963,41.178 64.017,41.183 64.027,41.182 69.485,46.64 69.527,46.674 69.575,46.7 69.626,46.715 69.68,46.721 70.03,46.721 72.945,49.636 72.884,49.668

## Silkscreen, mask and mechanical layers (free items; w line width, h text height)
Top Overlay:
  text "3V3 • SWD • 2L" at 37.4,62.9 h0.48
  text "I2C 0x38 • USB-C UART" at 78.4,62.9 h0.5
  text "MSPM0G3507SPMR + CH340N" at 48.4,28.525 h0.52
  text "AHT20" at 81.4,28.525 h0.55
  text "QUICK CONFIGURE • SENSOR BOARD" at 64.4,27.9 h0.65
